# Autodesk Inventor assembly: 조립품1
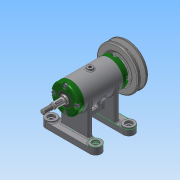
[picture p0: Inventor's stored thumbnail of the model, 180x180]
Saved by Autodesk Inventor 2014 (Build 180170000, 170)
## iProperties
Created: 2015-11
Part Number: 조립품1
Document SubType Name: Assembly
Designer: net
Author: net
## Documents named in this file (12)
- C:\Users\net\Desktop\451109v1036\조립품1.iam
- C:\Users\net\Desktop\451109v1036\본체.ipt
- C:\Users\net\Desktop\451109v1036\커버.ipt
- C:\Users\net\Desktop\451109v1036\볼트 M4 x 12.ipt
- C:\Users\net\Desktop\451109v1036\베어링 15 x 32 x 9.ipt
- C:\Users\net\Desktop\451109v1036\축.ipt
- C:\Users\net\Desktop\451109v1036\오일 실 15 25 7.ipt
- C:\Users\net\Desktop\451109v1036\키 3 x 3 x 12.ipt
- C:\Users\net\Desktop\451109v1036\V벨트풀리.ipt
- C:\Users\net\Desktop\451109v1036\와셔 8x17.ipt
- C:\Users\net\Desktop\451109v1036\스프링와셔 8.ipt
- C:\Users\net\Desktop\451109v1036\너트 M 8.ipt
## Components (11 placed, 3 different names)
1. KS B 2023 6002 - 15 x 32 x 9:1
2. KS B 2023 6002 - 15 x 32 x 9:2
3. V벨트풀리:1 — 각도:3
4. ISO 4762 M4 x 12:1
5. ISO 4762 M4 x 12:2
6. ISO 4762 M4 x 12:3
7. ISO 4762 M4 x 12:4
8. ISO 4762 M4 x 12:5
9. ISO 4762 M4 x 12:6
10. ISO 4762 M4 x 12:7
11. ISO 4762 M4 x 12:8
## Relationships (1: Angle 1)
- 각도:3 [Angle]: V벨트풀리:1
